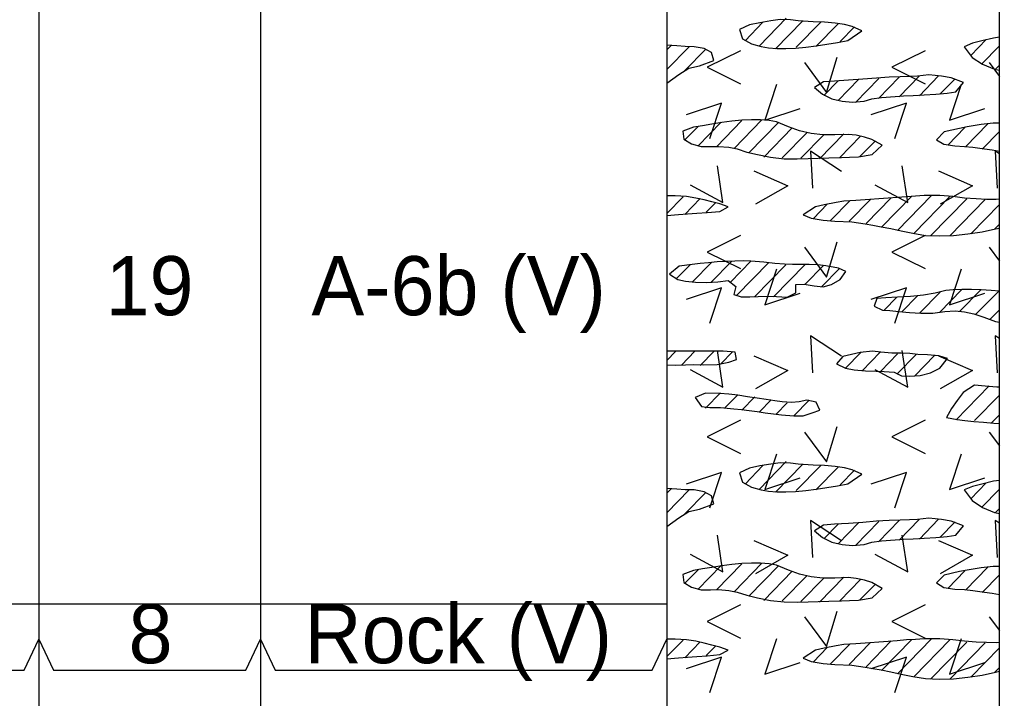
# Model space of a CAD drawing. Extents: x 0 to 0.83, y -0.65 to 1.27.
# Drawn here: x 0.7228 to 0.8333, y 0.2046 to 0.2811 of the extents above; entities that cross this region are included whole.
import ezdxf

# ---------------------------------------------------------------- set-up
doc = ezdxf.new("R2010")
doc.units = 0

msp = doc.modelspace()

# ---------------------------------------------------------------- linework, layer by layer
for points in [[(0, 0), (0.83333, 0), (0.83333, 1.275), (0, 1.275)], [(0, 0), (0.83333, 0), (0.83333, 1.275), (0, 1.275)], [(0, 0), (0.83333, 0), (0.83333, 1.275), (0, 1.275)], [(0, 0), (0.83333, 0), (0.83333, 1.275), (0, 1.275)], [(0, 0), (0.83333, 0), (0.83333, 1.275), (0, 1.275)], [(0.81233, 0.28087), (0.81063, 0.28099), (0.80977, 0.28112), (0.8086, 0.28113), (0.80755, 0.28099), (0.80632, 0.28079), (0.80513, 0.28054), (0.80403, 0.28002), (0.80436, 0.27896), (0.80536, 0.2784), (0.80647, 0.2781), (0.8073, 0.27795), (0.80824, 0.27787), (0.80926, 0.27786), (0.81035, 0.27791), (0.81149, 0.27801), (0.81267, 0.27816), (0.81386, 0.27835), (0.81506, 0.27856), (0.81625, 0.27879), (0.81783, 0.27987), (0.81673, 0.28037), (0.81585, 0.28057), (0.8148, 0.28073), (0.81361, 0.28083)], [(0.83265, 0.27906), (0.83136, 0.27875), (0.83028, 0.27847), (0.82934, 0.27808), (0.83026, 0.27688), (0.83142, 0.27612), (0.83279, 0.27554), (0.83333, 0.27544), (0.83333, 0.27915)], [(0.79583, 0.27396), (0.79719, 0.27495), (0.79831, 0.27565), (0.79951, 0.27593), (0.80111, 0.27653), (0.80086, 0.27741), (0.80002, 0.27789), (0.79889, 0.27808), (0.79791, 0.27811), (0.79694, 0.27817), (0.79583, 0.27825)], [(0.82537, 0.27491), (0.82408, 0.27476), (0.82319, 0.2747), (0.82214, 0.27467), (0.82091, 0.27464), (0.81947, 0.27454), (0.81792, 0.27442), (0.81632, 0.2743), (0.81475, 0.27421), (0.81348, 0.27411), (0.81247, 0.27347), (0.81337, 0.27271), (0.81444, 0.27221), (0.81561, 0.27192), (0.81675, 0.27181), (0.81807, 0.27193), (0.81896, 0.2722), (0.82003, 0.27235), (0.82157, 0.27247), (0.82253, 0.27253), (0.82362, 0.27258), (0.82483, 0.27265), (0.82618, 0.27271), (0.82745, 0.27282), (0.82842, 0.27299), (0.82927, 0.27405), (0.82791, 0.27457), (0.82679, 0.27477)], [(0.79885, 0.269), (0.79763, 0.26854), (0.79773, 0.26764), (0.79859, 0.26712), (0.7997, 0.26682), (0.80074, 0.26683), (0.80165, 0.26684), (0.80281, 0.26676), (0.80377, 0.26655), (0.80486, 0.2662), (0.80606, 0.26591), (0.80751, 0.26563), (0.80905, 0.26545), (0.81052, 0.26542), (0.81177, 0.26547), (0.81289, 0.26551), (0.81408, 0.26555), (0.81553, 0.26559), (0.81642, 0.26562), (0.81745, 0.26565), (0.81897, 0.26592), (0.82011, 0.26696), (0.81896, 0.26763), (0.8181, 0.26789), (0.81717, 0.26809), (0.81626, 0.26819), (0.81479, 0.26814), (0.81343, 0.26814), (0.8121, 0.26829), (0.8108, 0.26859), (0.80953, 0.26905), (0.8082, 0.2696), (0.80736, 0.26976), (0.8064, 0.26984), (0.80536, 0.26984), (0.80427, 0.26978), (0.80314, 0.26967), (0.80201, 0.26952), (0.8009, 0.26935), (0.79984, 0.26917)], [(0.83263, 0.26944), (0.83126, 0.26931), (0.82969, 0.26904), (0.82883, 0.26887), (0.82712, 0.26846), (0.82623, 0.26759), (0.82708, 0.2671), (0.82831, 0.26691), (0.82941, 0.26684), (0.83033, 0.26675), (0.83165, 0.26657), (0.83253, 0.26643), (0.83333, 0.26629), (0.83333, 0.26944)], [(0.79583, 0.25904), (0.79715, 0.25915), (0.79814, 0.25922), (0.79922, 0.2593), (0.80039, 0.25939), (0.80179, 0.25951), (0.80275, 0.26002), (0.80179, 0.26036), (0.80091, 0.26058), (0.80003, 0.2608), (0.79909, 0.26101), (0.79803, 0.26117), (0.79677, 0.26127), (0.79583, 0.26125)], [(0.82816, 0.25679), (0.82978, 0.25696), (0.83137, 0.25721), (0.8329, 0.25752), (0.83333, 0.25763), (0.83333, 0.26087), (0.83295, 0.26084), (0.83188, 0.26086), (0.83071, 0.26091), (0.82938, 0.26101), (0.82807, 0.26118), (0.82662, 0.2613), (0.82576, 0.2613), (0.82484, 0.26128), (0.82387, 0.26123), (0.82286, 0.26116), (0.82182, 0.26108), (0.82077, 0.26099), (0.81973, 0.26091), (0.81872, 0.26084), (0.81715, 0.26074), (0.81579, 0.26065), (0.81491, 0.26052), (0.81357, 0.26024), (0.8126, 0.26003), (0.81121, 0.25911), (0.8121, 0.25875), (0.81345, 0.2585), (0.81479, 0.25841), (0.81668, 0.25831), (0.81818, 0.25811), (0.81905, 0.25796), (0.82, 0.25778), (0.82107, 0.25757), (0.82225, 0.25732), (0.82357, 0.25703), (0.82501, 0.2568), (0.82656, 0.25673)], [(0.79708, 0.25181), (0.79794, 0.25163), (0.79904, 0.25152), (0.80028, 0.25149), (0.80156, 0.25154), (0.80274, 0.2517), (0.80361, 0.25103), (0.80338, 0.25014), (0.80422, 0.24987), (0.80517, 0.24985), (0.80613, 0.2499), (0.8072, 0.24993), (0.80818, 0.2499), (0.80939, 0.24983), (0.81037, 0.2503), (0.81038, 0.25124), (0.8113, 0.2513), (0.81244, 0.25112), (0.81346, 0.25101), (0.81438, 0.25127), (0.81539, 0.25181), (0.81601, 0.25272), (0.81517, 0.2531), (0.81374, 0.25337), (0.81285, 0.25346), (0.81187, 0.25352), (0.81, 0.25352), (0.8091, 0.25354), (0.808, 0.25362), (0.80678, 0.25377), (0.8053, 0.2539), (0.80443, 0.25392), (0.80349, 0.2539), (0.80251, 0.25386), (0.80152, 0.2538), (0.80054, 0.25372), (0.79959, 0.25363), (0.7987, 0.25353), (0.79722, 0.25331), (0.79614, 0.25243)], [(0.83241, 0.25059), (0.83129, 0.25066), (0.83017, 0.25069), (0.8291, 0.2507), (0.82811, 0.25066), (0.82728, 0.25057), (0.82608, 0.25027), (0.82476, 0.25004), (0.8233, 0.24991), (0.82183, 0.24982), (0.82051, 0.24976), (0.81951, 0.24967), (0.81922, 0.2488), (0.82013, 0.24838), (0.82097, 0.24833), (0.822, 0.24823), (0.82318, 0.2481), (0.82448, 0.24801), (0.82584, 0.24804), (0.82719, 0.2482), (0.82836, 0.24827), (0.8294, 0.24819), (0.83043, 0.24795), (0.83156, 0.24756), (0.83291, 0.24707), (0.83333, 0.247), (0.83333, 0.25052)], [(0.79583, 0.24218), (0.79676, 0.24217), (0.79792, 0.24219), (0.79882, 0.24223), (0.79992, 0.24218), (0.80151, 0.24223), (0.80282, 0.24248), (0.80367, 0.2428), (0.80354, 0.24364), (0.80216, 0.24373), (0.79583, 0.24373)], [(0.81822, 0.24153), (0.81944, 0.24147), (0.82033, 0.24143), (0.82145, 0.24137), (0.82229, 0.24095), (0.82324, 0.24091), (0.82438, 0.24101), (0.82555, 0.2413), (0.82662, 0.24181), (0.82749, 0.2429), (0.82651, 0.24321), (0.82524, 0.24331), (0.82413, 0.24337), (0.82324, 0.24348), (0.82226, 0.2435), (0.82121, 0.24352), (0.81995, 0.24361), (0.81902, 0.24373), (0.81761, 0.24359), (0.81566, 0.24314), (0.81496, 0.24231), (0.81598, 0.24182), (0.81695, 0.24164)], [(0.83305, 0.23968), (0.83171, 0.23979), (0.83054, 0.23989), (0.82925, 0.23907), (0.82857, 0.23816), (0.82792, 0.23727), (0.82735, 0.23625), (0.82858, 0.23602), (0.82945, 0.23592), (0.83045, 0.23582), (0.83155, 0.23573), (0.83272, 0.23563), (0.83333, 0.23558), (0.83333, 0.23967)], [(0.80066, 0.23738), (0.80188, 0.23737), (0.80339, 0.23724), (0.80423, 0.23715), (0.8051, 0.23704), (0.806, 0.23692), (0.80692, 0.2368), (0.80784, 0.23668), (0.80875, 0.23657), (0.81014, 0.23643), (0.81119, 0.23644), (0.81222, 0.23678), (0.81308, 0.23707), (0.81267, 0.23797), (0.8116, 0.23822), (0.81075, 0.23802), (0.80989, 0.23794), (0.80885, 0.23802), (0.80799, 0.23813), (0.80703, 0.23827), (0.806, 0.23844), (0.80492, 0.2386), (0.80384, 0.23876), (0.8028, 0.23889), (0.80182, 0.23898), (0.8002, 0.23899), (0.79901, 0.23852), (0.79974, 0.23748)], [(0.81233, 0.23087), (0.81063, 0.23099), (0.80977, 0.23112), (0.8086, 0.23113), (0.80755, 0.23099), (0.80632, 0.23079), (0.80513, 0.23054), (0.80403, 0.23002), (0.80436, 0.22896), (0.80536, 0.2284), (0.80647, 0.2281), (0.8073, 0.22795), (0.80824, 0.22787), (0.80926, 0.22786), (0.81035, 0.22791), (0.81149, 0.22801), (0.81267, 0.22816), (0.81386, 0.22835), (0.81506, 0.22856), (0.81625, 0.22879), (0.81783, 0.22987), (0.81673, 0.23037), (0.81585, 0.23057), (0.8148, 0.23073), (0.81361, 0.23083)], [(0.83265, 0.22906), (0.83136, 0.22875), (0.83028, 0.22847), (0.82934, 0.22808), (0.83026, 0.22688), (0.83142, 0.22612), (0.83279, 0.22554), (0.83333, 0.22544), (0.83333, 0.22915)], [(0.79583, 0.22396), (0.79719, 0.22495), (0.79831, 0.22565), (0.79951, 0.22593), (0.80111, 0.22653), (0.80086, 0.22741), (0.80002, 0.22789), (0.79889, 0.22808), (0.79791, 0.22811), (0.79694, 0.22817), (0.79583, 0.22825)], [(0.82537, 0.22491), (0.82408, 0.22476), (0.82319, 0.2247), (0.82214, 0.22467), (0.82091, 0.22464), (0.81947, 0.22455), (0.81792, 0.22442), (0.81632, 0.2243), (0.81475, 0.22421), (0.81348, 0.22411), (0.81247, 0.22347), (0.81337, 0.22271), (0.81444, 0.22221), (0.81561, 0.22192), (0.81675, 0.22181), (0.81807, 0.22193), (0.81896, 0.2222), (0.82003, 0.22235), (0.82157, 0.22247), (0.82253, 0.22253), (0.82362, 0.22258), (0.82483, 0.22265), (0.82618, 0.22271), (0.82745, 0.22282), (0.82842, 0.22299), (0.82927, 0.22405), (0.82791, 0.22457), (0.82679, 0.22477)], [(0.79885, 0.219), (0.79763, 0.21854), (0.79773, 0.21764), (0.79859, 0.21712), (0.7997, 0.21682), (0.80074, 0.21683), (0.80165, 0.21684), (0.80281, 0.21676), (0.80377, 0.21655), (0.80486, 0.2162), (0.80606, 0.21591), (0.80751, 0.21563), (0.80905, 0.21545), (0.81052, 0.21542), (0.81177, 0.21547), (0.81289, 0.21552), (0.81408, 0.21555), (0.81553, 0.21559), (0.81642, 0.21562), (0.81745, 0.21565), (0.81897, 0.21592), (0.82011, 0.21696), (0.81896, 0.21763), (0.8181, 0.21789), (0.81717, 0.21809), (0.81626, 0.2182), (0.81479, 0.21814), (0.81343, 0.21814), (0.8121, 0.21829), (0.8108, 0.21859), (0.80953, 0.21905), (0.8082, 0.2196), (0.80736, 0.21976), (0.8064, 0.21984), (0.80536, 0.21984), (0.80427, 0.21978), (0.80314, 0.21967), (0.80201, 0.21952), (0.8009, 0.21935), (0.79984, 0.21917)], [(0.83263, 0.21944), (0.83126, 0.21931), (0.82969, 0.21904), (0.82883, 0.21887), (0.82712, 0.21846), (0.82623, 0.21759), (0.82708, 0.2171), (0.82831, 0.21691), (0.82941, 0.21684), (0.83033, 0.21675), (0.83165, 0.21657), (0.83253, 0.21643), (0.83333, 0.21629), (0.83333, 0.21944)], [(0.79583, 0.20904), (0.79715, 0.20915), (0.79814, 0.20922), (0.79922, 0.2093), (0.80039, 0.20939), (0.80179, 0.20951), (0.80275, 0.21002), (0.80179, 0.21036), (0.80091, 0.21058), (0.80003, 0.2108), (0.79909, 0.21101), (0.79803, 0.21117), (0.79677, 0.21127), (0.79583, 0.21125)], [(0.82816, 0.20679), (0.82978, 0.20696), (0.83137, 0.20721), (0.8329, 0.20752), (0.83333, 0.20763), (0.83333, 0.21087), (0.83295, 0.21084), (0.83188, 0.21086), (0.83071, 0.21091), (0.82938, 0.21101), (0.82807, 0.21118), (0.82662, 0.2113), (0.82576, 0.2113), (0.82484, 0.21128), (0.82387, 0.21123), (0.82286, 0.21116), (0.82182, 0.21108), (0.82077, 0.21099), (0.81973, 0.21091), (0.81872, 0.21084), (0.81715, 0.21074), (0.81579, 0.21065), (0.81491, 0.21052), (0.81357, 0.21024), (0.8126, 0.21003), (0.81121, 0.20911), (0.8121, 0.20875), (0.81345, 0.2085), (0.81479, 0.20841), (0.81668, 0.20831), (0.81818, 0.20811), (0.81905, 0.20796), (0.82, 0.20778), (0.82107, 0.20757), (0.82225, 0.20732), (0.82357, 0.20703), (0.82501, 0.2068), (0.82656, 0.20673)]]:
    msp.add_lwpolyline(points, close=True)
for points in [[(0.725, 1.22083), (0.725, -0.64575)], [(0.75, 1.22083), (0.75, -0.64575)], [(0.75, 1.22083), (0.75, -0.64575)], [(0.79583, 1.22083), (0.79583, -0.64575)], [(0.725, 1.20833), (0.725, -0.64575)], [(0.83333, -0.64575), (0.83333, 1.13365)], [(0.80465, 0.27875), (0.80667, 0.28083)], [(0.80626, 0.27819), (0.80928, 0.28128)], [(0.80809, 0.27785), (0.81111, 0.28095)], [(0.81041, 0.27802), (0.81318, 0.28085)], [(0.81264, 0.27809), (0.81518, 0.28069)], [(0.81536, 0.27867), (0.81699, 0.28033)], [(0.8301, 0.27709), (0.83184, 0.27888)], [(0.7963, 0.27821), (0.79583, 0.27772)], [(0.79834, 0.27808), (0.79583, 0.27551)], [(0.79786, 0.27538), (0.80023, 0.27781)], [(0.80412, 0.27763), (0.80038, 0.27576), (0.80412, 0.27388)], [(0.82496, 0.27763), (0.82121, 0.27576), (0.82496, 0.27388)], [(0.83131, 0.27612), (0.83333, 0.27819)], [(0.81134, 0.27629), (0.81384, 0.27291), (0.81503, 0.27691)], [(0.83217, 0.27629), (0.83333, 0.27473)], [(0.83285, 0.27549), (0.83333, 0.27598)], [(0.81519, 0.27428), (0.81354, 0.27258)], [(0.81514, 0.27201), (0.81748, 0.27441)], [(0.81709, 0.2718), (0.81974, 0.27451)], [(0.8197, 0.27225), (0.82203, 0.27465)], [(0.82202, 0.27242), (0.8243, 0.27475)], [(0.82431, 0.27255), (0.82644, 0.27474)], [(0.82663, 0.27271), (0.82834, 0.27447)], [(0.80818, 0.2738), (0.80687, 0.2698), (0.81087, 0.27111)], [(0.82901, 0.2738), (0.8277, 0.2698), (0.8317, 0.27111)], [(0.80069, 0.26772), (0.802, 0.27172), (0.798, 0.27041)], [(0.82152, 0.26772), (0.82284, 0.27172), (0.81884, 0.27041)], [(0.80142, 0.2668), (0.8043, 0.26975)], [(0.80653, 0.26983), (0.8034, 0.26661)], [(0.79938, 0.26913), (0.79786, 0.26758)], [(0.79933, 0.26687), (0.80195, 0.26956)], [(0.80506, 0.2661), (0.8084, 0.26952)], [(0.80997, 0.26893), (0.80675, 0.26562)], [(0.82751, 0.26698), (0.82945, 0.26896)], [(0.83203, 0.26939), (0.82949, 0.26679)], [(0.81164, 0.26842), (0.80884, 0.26556)], [(0.81353, 0.26814), (0.81094, 0.26549)], [(0.81303, 0.26542), (0.81579, 0.26825)], [(0.81534, 0.26558), (0.81768, 0.26797)], [(0.8176, 0.26568), (0.81934, 0.26747)], [(0.83138, 0.26652), (0.83333, 0.26852)], [(0.81551, 0.26399), (0.81201, 0.26631), (0.81226, 0.26212)], [(0.83333, 0.26598), (0.83284, 0.26631), (0.83309, 0.26212)], [(0.83333, 0.2663), (0.83333, 0.26631)], [(0.79847, 0.26251), (0.80215, 0.26051), (0.80153, 0.26464)], [(0.8193, 0.26251), (0.82299, 0.26051), (0.82236, 0.26464)], [(0.80562, 0.26406), (0.80946, 0.26237), (0.80581, 0.26031)], [(0.82645, 0.26406), (0.83029, 0.26237), (0.82664, 0.26031)], [(0.79765, 0.26115), (0.79583, 0.25928)], [(0.7996, 0.26094), (0.79786, 0.25915)], [(0.8164, 0.25841), (0.81879, 0.26086)], [(0.81829, 0.25813), (0.82114, 0.26105)], [(0.82004, 0.25771), (0.82346, 0.26122)], [(0.82569, 0.26129), (0.82184, 0.25735)], [(0.82775, 0.26119), (0.8237, 0.25705)], [(0.82964, 0.26092), (0.82557, 0.25674)], [(0.83173, 0.26085), (0.82774, 0.25676)], [(0.8013, 0.26046), (0.80027, 0.25941)], [(0.81392, 0.2603), (0.81235, 0.25869)], [(0.8143, 0.25848), (0.8165, 0.26073)], [(0.83333, 0.26027), (0.83012, 0.25698)], [(0.83281, 0.25752), (0.83333, 0.25806)], [(0.80412, 0.2568), (0.80038, 0.25492), (0.80412, 0.25305)], [(0.82496, 0.2568), (0.82121, 0.25492), (0.82496, 0.25305)], [(0.81134, 0.25546), (0.81384, 0.25208), (0.81503, 0.25608)], [(0.83217, 0.25546), (0.83333, 0.2539)], [(0.79844, 0.25349), (0.79691, 0.25192)], [(0.79871, 0.25155), (0.80085, 0.25374)], [(0.80083, 0.25151), (0.80311, 0.25385)], [(0.80534, 0.25392), (0.80299, 0.25151)], [(0.80367, 0.25), (0.80732, 0.25374)], [(0.80571, 0.24988), (0.80924, 0.25349)], [(0.81142, 0.25351), (0.80785, 0.24986)], [(0.81141, 0.25129), (0.81348, 0.25341)], [(0.80818, 0.25297), (0.80687, 0.24897), (0.81087, 0.25028)], [(0.81528, 0.25305), (0.81331, 0.25103)], [(0.82901, 0.25297), (0.8277, 0.24897), (0.8317, 0.25028)], [(0.80069, 0.24689), (0.802, 0.25089), (0.798, 0.24957)], [(0.82152, 0.24689), (0.82284, 0.25089), (0.81884, 0.24957)], [(0.82035, 0.24837), (0.82176, 0.24982)], [(0.82233, 0.24819), (0.82408, 0.24998)], [(0.82433, 0.24802), (0.82666, 0.25041)], [(0.82909, 0.2507), (0.82656, 0.2481)], [(0.82885, 0.24823), (0.83122, 0.25066)], [(0.83325, 0.25052), (0.83065, 0.24786)], [(0.83333, 0.2484), (0.83227, 0.24731)], [(0.81551, 0.24316), (0.81201, 0.24547), (0.81226, 0.24128)], [(0.83333, 0.24515), (0.83284, 0.24547), (0.83309, 0.24128)], [(0.79583, 0.2427), (0.79681, 0.2437)], [(0.79898, 0.24372), (0.79747, 0.24217)], [(0.79847, 0.24168), (0.80215, 0.23968), (0.80153, 0.2438)], [(0.80116, 0.24373), (0.79959, 0.24213)], [(0.80328, 0.24369), (0.80188, 0.24226)], [(0.80562, 0.24322), (0.80946, 0.24154), (0.80581, 0.23948)], [(0.8177, 0.24359), (0.81596, 0.24181)], [(0.81988, 0.24361), (0.81785, 0.24153)], [(0.8193, 0.24168), (0.82299, 0.23968), (0.82236, 0.2438)], [(0.82185, 0.24342), (0.81997, 0.24149)], [(0.824, 0.24341), (0.82178, 0.24113)], [(0.82601, 0.24325), (0.82378, 0.24097)], [(0.82645, 0.24322), (0.83029, 0.24154), (0.82664, 0.23948)], [(0.83217, 0.23981), (0.82844, 0.23599)], [(0.80188, 0.23903), (0.8002, 0.23731)], [(0.8038, 0.23879), (0.80237, 0.23733)], [(0.83333, 0.23879), (0.83052, 0.23591)], [(0.80575, 0.23857), (0.80429, 0.23708)], [(0.80758, 0.23824), (0.80627, 0.23689)], [(0.80941, 0.2379), (0.80816, 0.23662)], [(0.81188, 0.23821), (0.81016, 0.23646)], [(0.83333, 0.23657), (0.83245, 0.23567)], [(0.80412, 0.23596), (0.80038, 0.23409), (0.80412, 0.23221)], [(0.82496, 0.23596), (0.82121, 0.23409), (0.82496, 0.23221)], [(0.81134, 0.23462), (0.81384, 0.23125), (0.81503, 0.23525)], [(0.83217, 0.23462), (0.83333, 0.23306)], [(0.80818, 0.23213), (0.80687, 0.22813), (0.81087, 0.22945)], [(0.82901, 0.23213), (0.8277, 0.22813), (0.8317, 0.22945)], [(0.80626, 0.22819), (0.80928, 0.23128)], [(0.80809, 0.22785), (0.81111, 0.23095)], [(0.80069, 0.22605), (0.802, 0.23005), (0.798, 0.22874)], [(0.80465, 0.22875), (0.80667, 0.23083)], [(0.81041, 0.22802), (0.81318, 0.23085)], [(0.81264, 0.22809), (0.81518, 0.23069)], [(0.81536, 0.22867), (0.81699, 0.23033)], [(0.82152, 0.22605), (0.82284, 0.23005), (0.81884, 0.22874)], [(0.8301, 0.22709), (0.83184, 0.22888)], [(0.7963, 0.22821), (0.79583, 0.22772)], [(0.79834, 0.22808), (0.79583, 0.22551)], [(0.79786, 0.22538), (0.80023, 0.22781)], [(0.83131, 0.22612), (0.83333, 0.22819)], [(0.83285, 0.22549), (0.83333, 0.22598)], [(0.81551, 0.22233), (0.81201, 0.22464), (0.81226, 0.22045)], [(0.81514, 0.22201), (0.81748, 0.22441)], [(0.81709, 0.2218), (0.81974, 0.22451)], [(0.8197, 0.22225), (0.82203, 0.22465)], [(0.82202, 0.22242), (0.8243, 0.22475)], [(0.82431, 0.22255), (0.82644, 0.22474)], [(0.82663, 0.22271), (0.82834, 0.22447)], [(0.83333, 0.22432), (0.83284, 0.22464), (0.83309, 0.22045)], [(0.81519, 0.22428), (0.81354, 0.22258)], [(0.79847, 0.22084), (0.80215, 0.21884), (0.80153, 0.22297)], [(0.80562, 0.22239), (0.80946, 0.22071), (0.80581, 0.21864)], [(0.8193, 0.22084), (0.82299, 0.21884), (0.82236, 0.22297)], [(0.82645, 0.22239), (0.83029, 0.22071), (0.82664, 0.21864)], [(0.79938, 0.21913), (0.79786, 0.21758)], [(0.79933, 0.21687), (0.80195, 0.21956)], [(0.80142, 0.2168), (0.8043, 0.21975)], [(0.80653, 0.21983), (0.8034, 0.21661)], [(0.80506, 0.2161), (0.8084, 0.21953)], [(0.80997, 0.21893), (0.80675, 0.21562)], [(0.82751, 0.21698), (0.82945, 0.21896)], [(0.83203, 0.21939), (0.82949, 0.21679)], [(0.81164, 0.21842), (0.80884, 0.21556)], [(0.81353, 0.21814), (0.81094, 0.21549)], [(0.81303, 0.21542), (0.81579, 0.21825)], [(0.81534, 0.21558), (0.81768, 0.21797)], [(0.83138, 0.21652), (0.83333, 0.21852)], [(0.8176, 0.21568), (0.81934, 0.21747)], [(0.83333, 0.2163), (0.83333, 0.21631)], [(0.70417, 0.21525), (0.725, 0.21525)], [(0.725, 0.21525), (0.75, 0.21525)], [(0.75, 0.21525), (0.79583, 0.21525)], [(0.80412, 0.21513), (0.80038, 0.21326), (0.80412, 0.21138)], [(0.81134, 0.21379), (0.81384, 0.21042), (0.81503, 0.21442)], [(0.82496, 0.21513), (0.82121, 0.21326), (0.82496, 0.21138)], [(0.83217, 0.21379), (0.83333, 0.21223)], [(0.70417, 0.21126), (0.70583, 0.20775), (0.72333, 0.20775), (0.725, 0.21126)], [(0.725, 0.21126), (0.72667, 0.20775), (0.74833, 0.20775), (0.75, 0.21126)], [(0.75, 0.21126), (0.75167, 0.20775), (0.79417, 0.20775), (0.79583, 0.21126)], [(0.79765, 0.21115), (0.79583, 0.20928)], [(0.80818, 0.2113), (0.80687, 0.2073), (0.81087, 0.20861)], [(0.82004, 0.20771), (0.82346, 0.21122)], [(0.82569, 0.21129), (0.82184, 0.20735)], [(0.82775, 0.21119), (0.8237, 0.20705)], [(0.82901, 0.2113), (0.8277, 0.2073), (0.8317, 0.20861)], [(0.7996, 0.21094), (0.79786, 0.20916)], [(0.8013, 0.21046), (0.80027, 0.20941)], [(0.81392, 0.2103), (0.81235, 0.20869)], [(0.8143, 0.20848), (0.8165, 0.21073)], [(0.8164, 0.20841), (0.81879, 0.21086)], [(0.81829, 0.20813), (0.82114, 0.21105)], [(0.82964, 0.21092), (0.82557, 0.20674)], [(0.83173, 0.21085), (0.82774, 0.20676)], [(0.83333, 0.21027), (0.83012, 0.20698)], [(0.80069, 0.20522), (0.802, 0.20922), (0.798, 0.20791)], [(0.82152, 0.20522), (0.82284, 0.20922), (0.81884, 0.20791)], [(0.83281, 0.20752), (0.83333, 0.20806)]]:
    msp.add_lwpolyline(points)

# ---------------------------------------------------------------- texts
for s, height, p in [('19', 0.006667, (0.73253, 0.24779)), ('A-6b (V)', 0.006667, (0.75575, 0.24779)), ('Rock (V)', 0.006667, (0.75497, 0.20854)), ('8', 0.00667, (0.73512, 0.20854))]:
    msp.add_text(s, height=height).set_placement(p)

doc.saveas('drawing.dxf')
